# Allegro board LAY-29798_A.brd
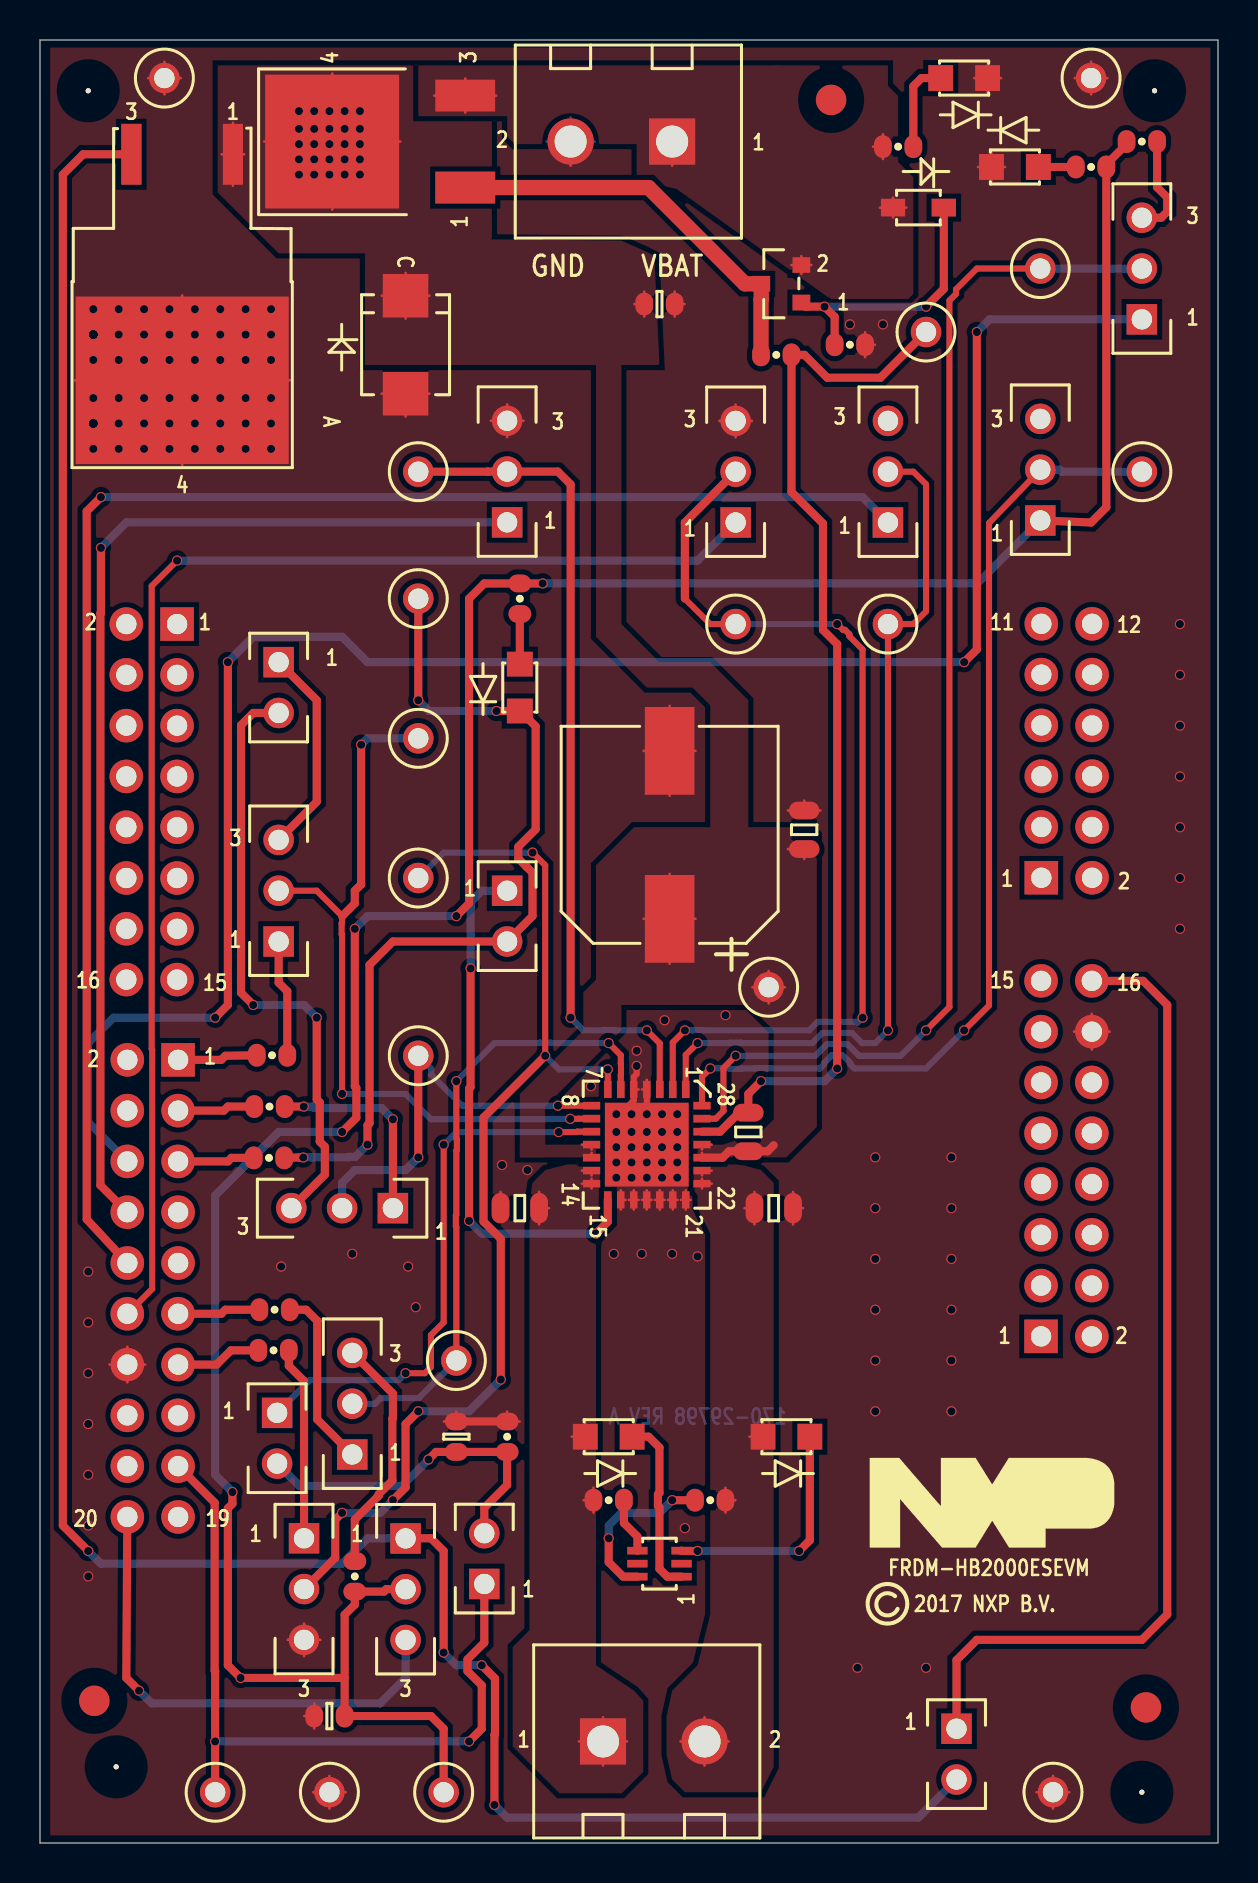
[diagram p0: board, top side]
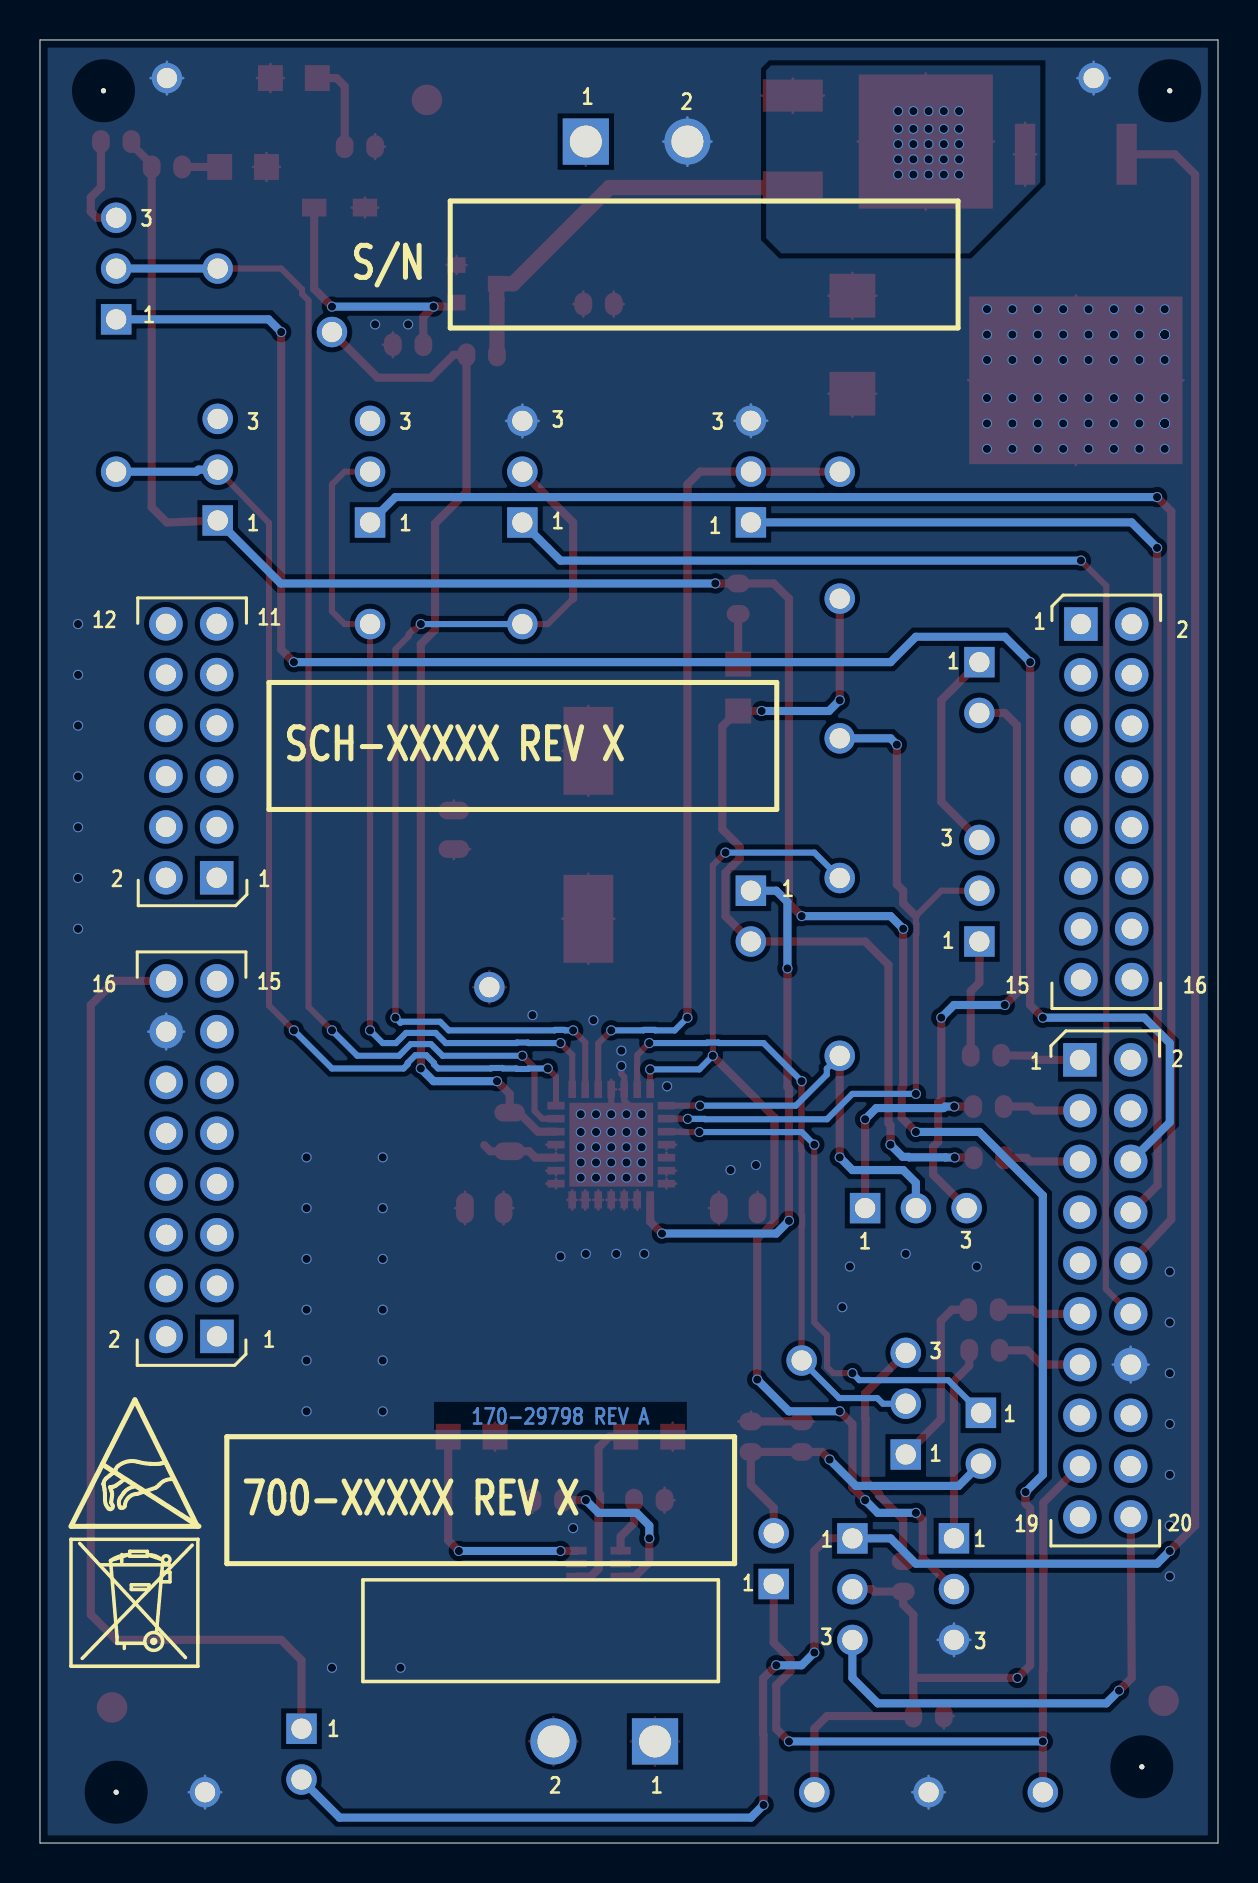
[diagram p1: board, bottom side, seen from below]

Outline 58.93 x 90.17 mm; copper layers: TOP, LAYER2, LAYER3, BOTTOM. Coordinates in mm from the lower left corner of the outline.
Outline path: 0,90.17 0,0 58.93,0 58.93,90.17 0,90.17

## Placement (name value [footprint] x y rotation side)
C1  0.1 UF  [CC0805_OV]  38.23 50.67 90 top
C2  100UF  [CAP_10DIA_10P5]  31.5 50.42 90 top
C3  0.1 UF  [CC0805_OV]  35.43 35.56 90 top
C4  0.033UF  [CC0805_OV]  36.7 31.75 0 top
C5  0.033UF  [CC0805_OV]  24 31.75 180 top
C7  0.33UF  [CC0603_OV]  30.99 76.96 0 top
C8  0.1uF  [CC0603_OV]  14.48 6.35 180 top
C9  0.047UF  [CC0603_OV]  20.83 20.32 90 top
CCP  TEST POINT BLACK  [TEST_LOOP]  44.32 75.56 0 top
CFB  HDR_1X2  [HDR102]  11.86 21.51 0 top
CFB_R  HDR_1X2  [HDR102]  22.22 12.95 180 top
CFB_V  TEST POINT BLACK  [TEST_LOOP]  8.76 2.54 0 top
CS_B  HDR_1X3  [HDR103]  55.12 76.2 180 top
CS_B1  TEST POINT BLACK  [TEST_LOOP]  50.04 78.74 0 top
D57  BAS70TW-7-F  [SC70-6]  30.99 13.97 90 top
D58  1N4148WS  [SOD323]  43.94 81.79 90 top
D59  SMBJ40  [DO-214AA_A]  18.29 74.93 270 top
DIS  HDR_1X3  [HDR103]  13.21 15.24 0 top
DIS1  TEST POINT BLACK  [TEST_LOOP]  18.92 48.26 0 top
ENBL  HDR_1X3  [HDR103]  15.62 19.43 180 top
ENBL1  TEST POINT BLACK  [TEST_LOOP]  20.83 24.13 0 top
EX_IN  HDR_1X2  [HDR102]  11.94 59.05 0 top
FS_B  RED  [LED2_2P34_2P1X1P25]  24 57.79 90 top
FS_B1  TEST POINT BLACK  [TEST_LOOP]  18.92 62.23 0 top
FS_B_  HDR_1X2  [HDR102]  23.37 47.62 0 top
FWD  GREEN  [LED2_2P34_2P1X1P25]  28.45 20.32 180 top
GND  TEST POINT BLACK  [TEST_LOOP]  50.67 2.54 0 top
GND1  TEST POINT BLACK  [TEST_LOOP]  14.48 2.54 0 top
GND2  TEST POINT BLACK  [TEST_LOOP]  6.22 88.27 0 top
GND3  TEST POINT BLACK  [TEST_LOOP]  52.58 88.27 0 top
IN1  HDR_1X3  [HDR103]  11.94 45.09 180 top
IN2  HDR_1X3  [HDR103]  17.65 31.75 270 top
IN_1  TEST POINT BLACK  [TEST_LOOP]  18.92 55.25 0 top
IN_2  TEST POINT BLACK  [TEST_LOOP]  18.92 39.37 0 top
J10  HDR_10X2  [HDR210]  6.91 39.17 180 bottom
J20  CON 1X2 TB TH  [CONN_2_TB_5P08_TH]  31.62 85.09 180 top
J23  HDR_2X6  [HDR206]  50.09 48.27 0 bottom
J24  HDR_2X8  [HDR208]  6.86 60.96 180 bottom
J25  HDR_2X8  [HDR208]  50.08 25.34 0 bottom
MISO  HDR_1X3  [HDR103]  42.42 66.04 180 top
MISO1  TEST POINT BLACK  [TEST_LOOP]  42.42 60.96 0 top
MOSI  HDR_1X3  [HDR103]  23.37 66.05 180 top
MOSI1  TEST POINT BLACK  [TEST_LOOP]  18.92 68.58 0 top
NOREF  -  [unnamed]  55.75 87.63 0 top
NOREF#2  -  [#2]  27.35 37.92 90 top
NOREF#3  -  [#2]  0 0 90 top
NOREF#4  -  [#2]  3.15 2.73 0 top
NOREF#5  -  [unnamed]  55.12 2.54 0 top
NOREF#6  -  [#2]  -232.03 -139.7 0 top
NOREF#7  -  [#2]  38.43 11.38 0 top
NOREF#8  -  [#2]  -345.44 312.17 0 top
NOREF#9  -  [unnamed]  3.81 3.81 0 top
NOREF#10  -  [unnamed]  55.32 6.78 0 top
NOREF#11  -  [unnamed]  2.72 7.11 0 top
NOREF#12  -  [#2]  0 90.17 0 top
NOREF#13  -  [#2]  21.77 38.14 0 top
NOREF#14  -  [#2]  28.4 32.16 0 top
NOREF#15  -  [#2]  28.4 32.16 90 top
NOREF#16  -  [#2]  28.4 32.16 90 top
NOREF#17  -  [#2]  28.4 32.16 0 top
NOREF#18  -  [unnamed]  39.57 87.17 0 top
NOREF#19  -  [#2]  46.15 12.32 0 top
NOREF#20  -  [#2]  41.5 14.77 0 top
NOREF#21  -  [#2]  27.35 37.92 90 top
NOREF#22  -  [#2]  -390.4 -204.85 0 top
NOREF#23  -  [#2]  58.93 0 90 top
NOREF#24  -  [#2]  21.35 43.92 0 top
NOREF#25  -  [#2]  -18.42 -37.46 0 top
NOREF#26  -  [#2]  79.04 90.25 0 top
NOREF#27  -  [#2]  -83.69 -91.31 0 top
NOREF#28  -  [#2]  37.82 8.05 0 top
NOREF#29  -  [#2]  31.5 54.62 270 top
NOREF#30  -  [unnamed]  2.41 87.63 0 top
NOREF#31  -  [#2]  21.35 43.92 0 top
NOREF#32  -  [#2]  0 0 0 top
NOREF#33  -  [#2]  56.77 14.1 180 bottom
NOREF#34  -  [#2]  54.86 4.58 180 bottom
NOREF#35  -  [#2]  42.77 8.08 180 bottom
NOREF#36  -  [#2]  91.19 56.69 180 bottom
NOREF#37  -  [#2]  95.55 47.22 180 bottom
NOREF#38  -  [#2]  92.1 65.66 180 bottom
OUT  CON 1X2 TB TH  [CONN_2_TB_5P08_TH]  28.16 5.08 0 top
Q1  IPD30N06S2-15  [TO252_DPAK_ST]  17.02 85.09 90 top
Q3  SMMBTA06LT1G  [SOT23_A]  37.08 77.98 90 top
R1  1M  [RC0603_OV]  36.83 74.42 0 top
R2  47K  [RC0603_OV]  40.51 74.93 0 top
R10  10K  [RC0603_OV]  42.93 84.84 0 top
R187  0  [RC0603_OV]  11.61 39.4 0 top
R188  0  [RC0603_OV]  11.48 36.83 0 top
R192  0  [RC0603_OV]  11.73 26.67 0 top
R193  0  [RC0603_OV]  11.68 24.64 0 top
R203  1K  [RC0603_OV]  33.53 17.14 0 top
R204  1K  [RC0603_OV]  28.45 17.14 0 top
R206  4.70K  [RC0603_OV]  24 62.23 270 top
R207  4.70K  [RC0603_OV]  52.58 83.82 180 top
R208  4.70K  [RC0603_OV]  55.12 85.09 180 top
R209  4.70K  [RC0603_OV]  15.75 13.34 270 top
R210  0  [RC0603_OV]  11.46 34.26 0 top
R212  200  [RC0603_OV]  23.37 20.32 90 top
REV  RED  [LED2_2P34_2P1X1P25]  37.34 20.32 180 top
SCLK  HDR_1X3  [HDR103]  34.8 66.04 180 top
SCLK1  TEST POINT BLACK  [TEST_LOOP]  34.8 60.96 0 top
U2  MC7805ABD2TG  [D2PAK]  7.11 73.66 180 top
U3  MC33HB2000ES  [QFN28_0P65_6X6_EP4P2]  30.35 34.92 270 top
VBAT  GREEN  [LED2_2P34_2P1X1P25]  46.23 88.27 180 top
VDD  HDR_1X3  [HDR103]  18.29 15.23 0 top
VDD1  TEST POINT BLACK  [TEST_LOOP]  20.19 2.54 0 top
VDD_  GREEN  [LED2_2P34_2P1X1P25]  48.77 83.82 0 top
VDD_REG  HDR_1X2  [HDR102]  45.85 5.71 0 top
VDDQ  HDR_1X3  [HDR103]  50.04 66.14 180 top
VDDQ1  TEST POINT BLACK  [TEST_LOOP]  55.12 68.58 0 top
VPWR  TEST POINT BLACK  [TEST_LOOP]  36.45 42.8 0 top

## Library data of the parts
C1 C3-C5 C7-C9 = CAP_NP
C2 = CAP_POL
CCP CFB_V CS_B1 DIS1 ENBL1 FS_B1 GND GND1-GND3 IN_1 IN_2 MISO1 MOSI1 SCLK1 VDD1 VDDQ1 VPWR = TestLoop
CFB CFB_R EX_IN FS_B_ J20 OUT VDD_REG = CONN_HDR_2X1
CS_B DIS ENBL IN1 IN2 MISO MOSI SCLK VDD VDDQ = Jumper 3Pin
D57 = BAS70TW
D58 = DIODE
D59 = DIODE_TVS
FS_B FWD REV VBAT VDD_ = LED
J10 = CONN_HDR_10X2
J23 = CONN_HDR_6X2
J24 J25 = CONN_HDR_8X2
Q1 = MOSFET_N_D4
Q3 = NPN
R1 R2 R10 R187 R188 R192 R193 R203 R204 R206-R210 R212 = RES
U2 = MC7805
U3 = MC33HB2000EP_QFN_28P

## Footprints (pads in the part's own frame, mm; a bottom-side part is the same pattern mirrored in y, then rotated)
CAP_10DIA_10P5
  rect 4.394x2.489 smd: 1(-4.2,0) 2(4.2,0)
CC0603_OV
  oval 0.889x1.143 smd: 1(-0.762,0) 2(0.762,0)
CC0805_OV
  oval 0.889x1.524 smd: 1(-0.965,0) 2(0.965,0)
CONN_2_TB_5P08_TH
  rect 2.311x2.311 hole 1.6: 1(0,0)
  round 2.311 hole 1.6: 2(5.08,0)
D2PAK
  rect 1.016x3.048 smd: 1(-2.54,-10.795) 3(2.54,-10.795)
  rect 10.668x8.382 smd: 4(0,0.508)
DO-214AA_A
  rect 2.184x2.286 smd: A(2.45,0) C(-2.45,0)
HDR102
  rect 1.524x1.524 hole 1.016: 1(0,0)
  round 1.524 hole 1.016: 2(0,-2.54)
HDR103
  rect 1.524x1.524 hole 1.016: 1(0,0)
  round 1.524 hole 1.016: 2(0,-2.54) 3(0,-5.08)
HDR206
  rect 1.676x1.676 hole 1.016: 1(0,0)
  round 1.676 hole 1.016: 2(2.54,0) 3(0,-2.54) 4(2.54,-2.54) 5(0,-5.08) 6(2.54,-5.08) 7(0,-7.62) 8(2.54,-7.62) 9(0,-10.16) 10(2.54,-10.16) 11(0,-12.7) 12(2.54,-12.7)
HDR208
  rect 1.676x1.676 hole 1.016: 1(0,0)
  round 1.676 hole 1.016: 2(2.54,0) 3(0,-2.54) 4(2.54,-2.54) 5(0,-5.08) 6(2.54,-5.08) 7(0,-7.62) 8(2.54,-7.62) 9(0,-10.16) 10(2.54,-10.16) 11(0,-12.7) 12(2.54,-12.7) 13(0,-15.24) 14(2.54,-15.24) 15(0,-17.78) 16(2.54,-17.78)
HDR210
  rect 1.676x1.676 hole 1.016: 1(0,0)
  round 1.676 hole 1.016: 2(2.54,0) 3(0,-2.54) 4(2.54,-2.54) 5(0,-5.08) 6(2.54,-5.08) 7(0,-7.62) 8(2.54,-7.62) 9(0,-10.16) 10(2.54,-10.16) 11(0,-12.7) 12(2.54,-12.7) 13(0,-15.24) 14(2.54,-15.24) 15(0,-17.78) 16(2.54,-17.78) 17(0,-20.32) 18(2.54,-20.32) 19(0,-22.86) 20(2.54,-22.86)
LED2_2P34_2P1X1P25
  rect 1.245x1.295 smd: A(1.172,0) C(-1.172,0)
QFN28_0P65_6X6_EP4P2
  rect 0.864x0.381 smd: 1(-2.763,1.95) 2(-2.763,1.3) 3(-2.763,0.65) 4(-2.763,0) 5(-2.763,-0.65) 6(-2.763,-1.3) 7(-2.763,-1.95) 15(2.763,-1.95) 16(2.763,-1.3) 17(2.763,-0.65) 18(2.763,0) 19(2.763,0.65) 20(2.763,1.3) 21(2.763,1.95)
  rect 0.381x0.864 smd: 8(-1.95,-2.763) 9(-1.3,-2.763) 10(-0.65,-2.763) 11(0,-2.763) 12(0.65,-2.763) 13(1.3,-2.763) 14(1.95,-2.763) 22(1.95,2.763) 23(1.3,2.763) 24(0.65,2.763) 25(0,2.763) 26(-0.65,2.763) 27(-1.3,2.763) 28(-1.95,2.763)
  rect 4.191x4.191 smd: 29(0,0)
RC0603_OV
  oval 0.889x1.143 smd: 1(-0.762,0) 2(0.762,0)
SC70-6
  rect 0.381x1.016 smd: 1(-0.65,-1.105) 2(0,-1.105) 3(0.65,-1.105) 4(0.65,1.105) 5(0,1.105) 6(-0.65,1.105)
SOD323
  rect 0.889x1.219 smd: A(0,1.27) C(0,-1.27)
SOT23_A
  rect 0.787x0.889 smd: 1(-0.94,-1.003) 2(0.94,-1.003) 3(0,1.003)
TEST_LOOP
  round 1.524 hole 1.016: 1(0,0)
TO252_DPAK_ST
  rect 1.6x2.997 smd: 1(-2.3,-4.253) 3(2.3,-4.253)
  rect 6.706x6.706 smd: 4(0,2.4)
unnamed
  round 0.254 hole 2.388 unplated: (0,0)

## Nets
GND: C1.2 C2.2 C4.2 C5.2 C7.2 C8.2 C9.2 D59.A DIS.3(PIN3) GND.1(PIN1) GND1.1(PIN1) GND2.1(PIN1) GND3.1(PIN1) J10.14 J20.2 J25.14(B7) MOSI.3(PIN3) R2.2 R212.2 SCLK.3(PIN3) U2.4(GND) U3.4(DGND) U3.5(AGND1) U3.16(PGND1) U3.17(PGND2) U3.18(PGND3) U3.19(PGND4) U3.20(PGND5) U3.21(AGND2) U3.29(EP) VBAT.C(CATHODE) VDD_.C(CATHODE)
VBATT: D58.A(ANODE) J20.1 Q1.3(SOURCE) Q3.2(EMITTER) R10.1
VDD: C8.1 R206.1 R207.1 R208.2 R209.2 VDD.2(PIN2) VDD1.1(PIN1) VDDQ.1(PIN1)
VDD_REG: U2.3(OUT) VDD.1(PIN1) VDD_REG.2
VDDQ: U3.28(VDDQ) VDDQ.2(PIN2) VDDQ1.1(PIN1)
CCP: C3.2 CCP.1(PIN1) R1.2 U3.26(CCP)
CFB: CFB.1 U3.10(CFB)
CFB_READ: CFB_R.1 CFB_V.1(PIN1) J10.17
CS_B: CS_B.2(PIN2) CS_B1.1(PIN1) U3.27(C\S\)
CTRL0: ENBL.1(PIN1) R192.2
CTRL1: DIS.1(PIN1) R193.2
DATA0: IN1.1(PIN1) R187.2
DATA1: IN2.1(PIN1) R188.2
DIS: DIS.2(PIN2) DIS1.1(PIN1) U3.7(DIS)
ENBL: ENBL.2(PIN2) ENBL1.1(PIN1) U3.6(ENBL)
EX_IN1: EX_IN.1 IN1.3(PIN3)
EX_IN2: EX_IN.2 IN2.3(PIN3)
FRDM_VDD: J10.20 VDD.3(PIN3)
FS_B: FS_B.C(CATHODE) FS_B1.1(PIN1) FS_B_.2 R210.2
IN1: IN1.2(PIN2) IN_1.1(PIN1) U3.9(IN1)
IN2: IN2.2(PIN2) IN_2.1(PIN1) U3.8(IN2)
MISO: MISO.2(PIN2) MISO1.1(PIN1) U3.1(MISO)
MOSI: MOSI.2(PIN2) MOSI1.1(PIN1) U3.3(MOSI)
OUT1: C5.1 FWD.A(ANODE) OUT.1 R204.1 U3.13(OUT1_1) U3.14(OUT1_2)
OUT2: C4.1 OUT.2 R203.2 REV.A(ANODE) U3.22(OUT2_1) U3.23(OUT2_2)
SCLK: SCLK.2(PIN2) SCLK1.1(PIN1) U3.2(SCLK)
SPI_CS_B: CS_B.1(PIN1) J10.6
SPI_MISO: J10.10 MISO.1(PIN1)
SPI_MOSI: J10.8 MOSI.1(PIN1)
SPI_SCLK: J10.12 SCLK.1(PIN1)
VPWR: C1.1 C2.1 C3.1 C7.1 D59.C Q1.4(DRAIN) U2.1(IN) U3.11(VPWR1) U3.12(VPWR2) U3.24(VPWR3) U3.25(VPWR4) VPWR.1(PIN1)
N15086994: Q1.1(GATE) Q3.3(COLLECTOR) R1.1
N15515059: ENBL.3(PIN3) R209.1
N15516808: CS_B.3(PIN3) R208.1
N15517603: C9.1 CFB.2 CFB_R.2 R212.1
N15519474: D57.1(A1) FWD.C(CATHODE)
N15519750: D57.3(A3) REV.C(CATHODE)
N15519985: D57.6(C1) R203.1
N15520366: D57.4(C3) R204.2
N15536961: D58.C(CATHODE) Q3.1(BASE) R2.1
N15544276: FS_B_.1 U3.15(F\S\)
N15562112: FS_B.A(ANODE) R206.2
N15568529: J25.16(B8) VDD_REG.1
N155139640: J10.1 R187.1
N155139642: J10.3 R188.1
N155139645: J10.5 R210.1
N155348671: R10.2 VBAT.A(ANODE)
N155584890: R207.2 VDD_.A(ANODE)
N1551396410: J10.11 R192.1
N1551396412: J10.13 R193.1

Pads without a net: D57 2 5; J10 2 4 7 9 15 16 18 19; J23 1 2 3 4 5 6 7 8 9 10 11 12; J24 1 2 3 4 5 6 7 8 9 10 11 12 13 14 15 16; J25 1 2 3 4 5 6 7 8 9 10 11 12 13 15; MISO 3; VDDQ 3

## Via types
v1: diameter 0.508, hole 0.406, TOP to BOTTOM, 242 vias

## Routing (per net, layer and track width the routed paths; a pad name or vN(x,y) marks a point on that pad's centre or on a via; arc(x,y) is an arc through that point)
GND: length 248.9
  TOP w0.127: 1.73,73.15 U2.4 ; U2.4 12.5,73.15 ; U2.4 7.11,77.39 ; U2.4 7.11,68.91 ; 34.8,70.31 SCLK.3 ; SCLK.3 33.98,71.12 ; SCLK.3 35.61,71.12 ; SCLK.3 34.8,71.93 ; GND.1 50.67,3.35 ; GND.1 49.86,2.54 ; GND.1 50.67,1.73 ; GND.1 51.49,2.54 ; 13.72,5.73 C8.2 ; C8.2 13.72,6.97 ; C8.2 13.22,6.35 ; 13.21,9.35 DIS.3 ; DIS.3 12.39,10.16 ; DIS.3 13.21,10.97 ; DIS.3 14.02,10.16 ; v1(5.21,72.26) v1(3.94,70.99) v1(2.67,69.72) ; 31.65,31.68 U3.20 ; U3.20 31.41,32.16 ; U3.20 31.89,32.16 ; U3.20 31.65,32.65 ; 22.55,71.13 MOSI.3 ; MOSI.3 23.37,71.94 ; MOSI.3 23.37,70.31 ; MOSI.3 24.18,71.13 ; C7.2 31.75,77.58 ; C7.2 31.75,76.34 ; C7.2 32.25,76.96 ; 41.28,74.31 R2.2 ; R2.2 41.28,75.55 ; R2.2 41.77,74.93 ; 51.76,88.27 GND3.1 ; GND3.1 52.58,89.08 ; GND3.1 52.58,87.45 ; GND3.1 53.39,88.27 ; U3.21 32.54,32.16 ; U3.21 32.3,31.68 ; U3.21 32.3,32.65 ; U3.21 32.06,32.16 ; 30.11,37.69 U3.4 30.35,38.17 ; v1(6.48,75.44) v1(5.21,76.71) ; v1(9.02,72.26) v1(10.29,70.99) v1(11.56,69.72) ; v1(3.94,72.26) v1(2.67,70.99) ; 23.99,21.08 R212.2 23.37,21.58 ; VBAT.C 47.4,88.96 ; VBAT.C 46.73,88.27 ; VBAT.C 48.07,88.27 ; VBAT.C 47.4,87.57 ; C2.2 31.5,56.87 ; C2.2 32.79,54.62 ; C2.2 31.5,52.37 ; C2.2 30.2,54.62 ; U3.16 29.29,32.16 ; U3.16 29.05,31.68 ; U3.16 29.05,32.65 ; 29.46,32.16 U3.17 ; U3.17 29.94,32.16 ; U3.17 29.7,32.65 ; U3.17 29.7,31.68 ; v1(6.48,72.26) v1(5.21,70.99) v1(3.94,69.72) ; v1(11.56,76.71) v1(10.29,75.44) v1(9.02,74.17) ; GND1.1 15.29,2.54 ; GND1.1 14.48,1.73 ; GND1.1 14.48,3.35 ; GND1.1 13.66,2.54 ; 20.21,21.08 C9.2 20.83,21.58 ; 37.41,51.64 C1.2 ; C1.2 38.23,52.13 ; C1.2 39.04,51.64 ; 47.6,83.12 VDD_.C ; VDD_.C 47.6,84.52 ; VDD_.C 46.92,83.82 ; VDD_.C 48.27,83.82 ; v1(30.35,33.27) v1(30.35,34.04) v1(30.35,34.8) U3.29 30.35,35.2 ; U3.19 31.24,32.16 ; U3.19 31,31.68 ; U3.19 30.76,32.16 ; U3.19 31,32.65 ; v1(10.29,72.26) v1(11.56,70.99) ; U3.5 29.94,37.69 ; GND2.1 7.04,88.27 ; GND2.1 5.41,88.27 ; GND2.1 6.22,87.45 ; GND2.1 6.22,89.08 ; 4.37,23.04 J10.14 ; J10.14 4.37,24.82 ; J10.14 3.48,23.93 ; J10.14 5.26,23.93 ; C5.2 23.04,32.56 ; v1(6.48,74.17) v1(5.21,75.44) v1(3.94,76.71) ; 17.09,72.48 D59.A ; D59.A 19.48,72.48 ; D59.A 18.29,71.34 ; v1(6.48,70.99) v1(5.21,69.72) ; v1(5.21,74.17) v1(3.94,75.44) v1(2.67,76.71) ; U3.18 30.59,32.16 ; U3.18 30.11,32.16 ; U3.18 30.35,32.65 ; U3.18 30.35,31.68 ; v1(10.29,76.71) v1(9.02,75.44) v1(7.75,74.17) ; 51.73,40.58 J25.14 ; J25.14 52.62,39.69 ; J25.14 53.51,40.58 ; J25.14 52.62,41.47 ; v1(10.29,69.72) v1(9.02,70.99) v1(7.75,72.26) ; v1(7.75,75.44) v1(9.02,76.71) ; C4.2 37.67,32.56 ; C4.2 38.16,31.75 ; C4.2 37.67,30.94 ; v1(10.29,74.17) v1(11.56,75.44) ; 26.54,83.88 J20.2 ; v1(7.75,70.99) v1(9.02,69.72) ; v1(3.94,74.17) v1(2.67,75.44)
  TOP w0.305: U3.4 v1(30.35,36.45) v1(30.35,35.56) 30.35,35.2 ; 30.35,35.15 30.18,35.15 29.95,35.39 29.95,35.78 29.76,35.97 28.74,35.97 28.42,36.28 28.42,36.62 28.66,36.86 29.42,36.86 29.7,37.14 U3.5 29.7,38.31 29.84,38.46 v1(29.84,38.86)
  TOP w0.406: C9.2 R212.2
  LAYER2 w0.127: J20.2 27.75,85.09 ; J20.2 25.34,85.09 ; J20.2 26.54,86.3 ; J20.2 26.54,83.88 ; 23.37,70.31 MOSI.3 ; MOSI.3 24.18,71.13 ; MOSI.3 22.55,71.13 ; MOSI.3 23.37,71.94 ; 13.21,9.35 DIS.3 ; DIS.3 12.39,10.16 ; DIS.3 14.02,10.16 ; DIS.3 13.21,10.97 ; 49.86,2.54 GND.1 ; GND.1 50.67,1.73 ; GND.1 51.49,2.54 ; GND.1 50.67,3.35 ; 3.48,23.93 J10.14 ; J10.14 5.26,23.93 ; J10.14 4.37,23.04 ; J10.14 4.37,24.82 ; 14.48,1.73 GND1.1 ; GND1.1 13.66,2.54 ; GND1.1 14.48,3.35 ; GND1.1 15.29,2.54 ; SCLK.3 35.61,71.12 ; SCLK.3 33.98,71.12 ; SCLK.3 34.8,71.93 ; SCLK.3 34.8,70.31 ; 51.76,88.27 GND3.1 ; GND3.1 53.39,88.27 ; GND3.1 52.58,87.45 ; GND3.1 52.58,89.08 ; GND2.1 7.04,88.27 ; GND2.1 5.41,88.27 ; GND2.1 6.22,87.45 ; GND2.1 6.22,89.08 ; 51.73,40.58 J25.14 ; J25.14 52.62,41.47 ; J25.14 52.62,39.69 ; J25.14 53.51,40.58
  LAYER3 w0.127: GND2.1 6.22,89.08 ; GND2.1 6.22,87.45 ; GND2.1 5.41,88.27 ; GND2.1 7.04,88.27 ; J20.2 26.54,86.3 ; J20.2 26.54,83.88 ; J20.2 27.75,85.09 ; J20.2 25.34,85.09 ; GND.1 51.49,2.54 ; GND.1 49.86,2.54 ; GND.1 50.67,3.35 ; GND.1 50.67,1.73 ; 52.62,39.69 J25.14 ; J25.14 52.62,41.47 ; J25.14 51.73,40.58 ; J25.14 53.51,40.58 ; GND1.1 15.29,2.54 ; GND1.1 14.48,1.73 ; GND1.1 13.66,2.54 ; GND1.1 14.48,3.35 ; 34.8,70.31 SCLK.3 ; SCLK.3 35.61,71.12 ; SCLK.3 34.8,71.93 ; SCLK.3 33.98,71.12 ; GND3.1 52.58,89.08 ; GND3.1 51.76,88.27 ; GND3.1 53.39,88.27 ; GND3.1 52.58,87.45 ; J10.14 4.37,24.82 ; J10.14 3.48,23.93 ; J10.14 4.37,23.04 ; J10.14 5.26,23.93 ; MOSI.3 24.18,71.13 ; MOSI.3 23.37,70.31 ; MOSI.3 23.37,71.94 ; MOSI.3 22.55,71.13 ; DIS.3 13.21,10.97 ; DIS.3 13.21,9.35 ; DIS.3 12.39,10.16 ; DIS.3 14.02,10.16
  BOTTOM w0.127: 33.98,71.12 SCLK.3 ; SCLK.3 35.61,71.12 ; SCLK.3 34.8,70.31 ; SCLK.3 34.8,71.93 ; 12.39,10.16 DIS.3 ; DIS.3 13.21,10.97 ; DIS.3 14.02,10.16 ; DIS.3 13.21,9.35 ; 5.41,88.27 GND2.1 ; GND2.1 6.22,89.08 ; GND2.1 6.22,87.45 ; GND2.1 7.04,88.27 ; MOSI.3 23.37,71.94 ; MOSI.3 23.37,70.31 ; MOSI.3 24.18,71.13 ; MOSI.3 22.55,71.13 ; J10.14 5.26,23.93 ; J10.14 3.48,23.93 ; J10.14 4.37,23.04 ; J10.14 4.37,24.82 ; 52.58,87.45 GND3.1 ; GND3.1 51.76,88.27 ; GND3.1 52.58,89.08 ; GND3.1 53.39,88.27 ; GND1.1 15.29,2.54 ; GND1.1 14.48,3.35 ; GND1.1 14.48,1.73 ; GND1.1 13.66,2.54 ; GND.1 51.49,2.54 ; GND.1 50.67,1.73 ; GND.1 49.86,2.54 ; GND.1 50.67,3.35 ; J25.14 52.62,41.47 ; J25.14 53.51,40.58 ; J25.14 52.62,39.69 ; J25.14 51.73,40.58 ; J20.2 26.54,86.3 ; J20.2 26.54,83.88 ; J20.2 27.75,85.09 ; J20.2 25.34,85.09
  vias: v1(2.41,28.57) v1(2.41,26.04) v1(2.41,23.49) v1(2.41,20.95) v1(2.41,18.41) v1(2.41,15.88) v1(2.41,13.34) v1(2.67,74.17) v1(2.67,72.26) v1(6.48,76.71) v1(6.48,69.72) v1(7.75,76.71) v1(7.75,69.72) v1(11.56,74.17) v1(11.56,72.26) v1(12.07,28.83) v1(15.62,29.46) v1(18.41,28.83) v1(18.8,26.8) v1(23.11,33.91) v1(24.38,33.66) v1(27.56,37.85) v1(28.7,29.46) v1(28.83,36.45) v1(28.83,35.56) v1(28.83,34.8) v1(28.83,34.04) v1(28.83,33.27) v1(29.59,36.45) v1(29.59,35.56) v1(29.59,34.8) v1(29.59,34.04) v1(29.59,33.27) v1(29.84,39.62) v1(30.1,29.46) v1(31.11,36.45) v1(31.11,35.56) v1(31.11,34.8) v1(31.11,34.04) v1(31.11,33.27) v1(31.24,41.15) v1(31.62,29.46) v1(31.88,36.45) v1(31.88,35.56) v1(31.88,34.8) v1(31.88,34.04) v1(31.88,33.27) v1(32.26,15.75) v1(32.89,29.34) v1(34.29,41.4) v1(40.51,75.95) v1(40.89,8.76) v1(41.78,34.29) v1(41.78,31.75) v1(41.78,29.21) v1(41.78,26.67) v1(41.78,24.13) v1(41.78,21.59) v1(42.16,75.95) v1(44.32,8.76) v1(45.59,34.29) v1(45.59,31.75) v1(45.59,29.21) v1(45.59,26.67) v1(45.59,24.13) v1(45.59,21.59) v1(57.02,60.96) v1(57.02,58.42) v1(57.02,55.88) v1(57.02,53.34) v1(57.02,50.8) v1(57.02,48.26) v1(57.02,45.72)
VBATT: length 11.9
  TOP w0.127: R10.1 42.16,85.46 ; R10.1 41.67,84.84 ; R10.1 42.16,84.21 ; 21.27,86.54 Q1.3 ; Q1.3 21.27,88.24 ; Q1.3 19.72,87.39 ; Q1.3 22.82,87.39 ; 42.67,81.29 D58.A ; D58.A 42.67,82.28 ; D58.A 42.01,81.79 ; D58.A 43.33,81.79 ; Q3.2 38.58,78.92 ; Q3.2 38.09,78.47 ; Q3.2 37.59,78.92 ; Q3.2 38.09,79.36 ; 31.62,83.88 J20.1
VDD: length 139.6
  TOP w0.406: v1(25.15,62.99) R206.1 22.22,62.99 21.46,62.23 21.46,46.99 v1(20.83,46.36) ; v1(15.11,35.56) 15.82,36.27 15.82,37.76 15.75,37.84 v1(15.75,45.72) ; 15.24,8.26 v1(10.03,8.26) 9.4,8.89 9.4,16.74 9.63,16.97 v1(9.63,17.55) ; 15.24,8.26 C8.1 19.56,6.35 20.19,5.71 VDD1.1 ; 15.24,8.26 15.24,11.42 15.75,11.93 R209.2 17.2,12.57 17.32,12.69 VDD.2 ; VDDQ.1 52.58,66.04 53.34,66.8 R207.1 53.34,83.95 54.36,84.96 R208.2
  BOTTOM w0.406: VDDQ.1 46.89,62.99 v1(25.15,62.99) ; v1(20.83,46.36) 16.38,46.36 v1(15.75,45.72) ; v1(9.63,17.55) 8.76,18.41 8.76,32.38 11.94,35.56 v1(15.11,35.56)
VDD_REG: length 130.7
  TOP w0.406: v1(22.1,8.89) 22.76,8.23 22.76,5.44 22.73,5.42 v1(22.73,1.91) ; U2.3 2.16,84.45 1.14,83.44 1.14,15.88 v1(2.41,14.61) ; v1(20.19,9.53) 20.19,14.61 19.56,15.24 18.29,15.24 VDD.1
  BOTTOM w0.406: VDD.1 16.38,15.23 15.11,13.97 3.05,13.97 v1(2.41,14.61) ; v1(22.73,1.91) 23.37,1.27 43.94,1.27 VDD_REG.2 ; v1(20.19,9.53) 20.83,8.89 v1(22.1,8.89)
VDDQ: length 50.9
  TOP w0.305: VDDQ.2 47.47,66.01 47.47,41.88 v1(46.23,40.64) ; U3.28 33.12,38.32 v1(33.53,38.73)
  BOTTOM w0.305: v1(33.53,38.73) 34.5,38.73 34.52,38.71 35.07,38.71 35.1,38.73 35.77,38.73 35.79,38.76 36.34,38.76 36.37,38.73 39.02,38.73 39.22,38.94 39.22,39.01 39.6,39.4 40.15,39.4 40.54,39.01 40.54,38.94 40.74,38.73 44.32,38.73 v1(46.23,40.64)
  BOTTOM w0.406: VDDQ1.1 51.1,68.58 51,68.68 VDDQ.2
CCP: length 53.4
  TOP w0.406: CCP.1 42.04,73.28 39.38,73.28 38.24,74.42 R1.2 37.59,67.56 39.17,65.99 39.17,60.67 39.88,59.95 v1(39.88,38.73) ; v1(36.07,38.1) 35.43,37.47 C3.2 34.97,36.53 34.02,35.57 U3.26
  BOTTOM w0.406: v1(39.88,38.73) 39.24,38.1 v1(36.07,38.1)
CFB: length 27.7
  TOP w0.305: v1(20.19,34.92) 20.19,26.04 19.56,25.4 19.56,23.8 19.25,23.49 v1(18.29,23.49) ; U3.10 26.87,35.57 26.85,35.55 v1(25.94,35.55)
  BOTTOM w0.305: v1(18.29,23.49) 17.94,23.15 13.5,23.15 CFB.1 ; v1(25.94,35.55) 20.82,35.55 v1(20.19,34.92)
CFB_READ: length 38.6
  TOP w0.406: J10.17 8.74,17.02 8.74,8.62 8.76,8.59 v1(8.76,5.08) CFB_V.1 ; v1(21.46,5.08) 22.1,5.71 22.1,7.88 21.39,8.6 21.39,9.18 22.22,10.02 CFB_R.1
  BOTTOM w0.406: v1(21.46,5.08) v1(8.76,5.08)
CS_B: length 62.2
  TOP w0.305: v1(44.32,40.64) 45.49,41.81 45.49,77.14 45.82,77.47 45.82,77.7 46.86,78.74 CS_B1.1 ; U3.27 33.81,36.22 34.19,36.61 34.19,38.76 v1(34.8,39.37)
  BOTTOM w0.305: v1(44.32,40.64) 43.05,39.37 40.97,39.37 40.38,39.95 39.37,39.95 38.79,39.37 v1(34.8,39.37)
  BOTTOM w0.406: CS_B1.1 CS_B.2
CTRL0: length 9
  TOP w0.406: R192.2 13.31,26.67 13.87,26.11 13.87,21.18 ENBL.1
CTRL1: length 9.7
  TOP w0.406: DIS.1 13.21,23.1 12.45,23.86 R193.2
DATA0: length 5.9
  TOP w0.406: R187.2 12.37,42.6 11.94,43.03 IN1.1
DATA1: length 10.1
  TOP w0.406: R188.2 v1(13.2,36.83) ; v1(17.65,36.2) IN2.1
  BOTTOM w0.406: v1(17.65,36.2) 17.09,36.75 13.73,36.75 13.65,36.83 v1(13.2,36.83)
DIS: length 56.1
  TOP w0.305: U3.7 v1(28.4,38.69) ; v1(24.64,49.53) 25.27,48.9 v1(25.27,39.37)
  TOP w0.406: v1(23.05,23.18) 23.05,30.22 22.19,31.08 22.19,36.28 v1(25.27,39.37) ; v1(17.65,17.14) 18.29,17.78 18.29,20.95 v1(18.92,21.59) ; DIS.2 14.77,14.26 14.77,16.17 v1(15.11,16.51)
  BOTTOM w0.305: v1(24.64,49.53) 20.19,49.53 DIS1.1 ; v1(25.27,39.37) 25.95,38.69 v1(28.4,38.69)
  BOTTOM w0.406: v1(15.11,16.51) 17.02,16.51 v1(17.65,17.14) ; v1(23.05,23.18) 21.46,21.59 v1(18.92,21.59)
ENBL: length 31.1
  TOP w0.305: ENBL1.1 20.83,30.82 20.8,30.84 20.8,31.39 20.83,31.41 20.83,34.63 20.85,34.65 20.85,35.2 20.83,35.22 v1(20.83,38.1) ; U3.6 29.05,38.41 29.06,38.42 29.06,38.96 29.05,38.97 29.05,39.4 v1(28.45,40.01)
  BOTTOM w0.305: ENBL.2 16.76,21.97 17.04,22.25 18.95,22.25 ENBL1.1 ; v1(20.83,38.1) 22.73,40.01 24.97,40.01 25,40.03 25.55,40.03 25.57,40.01 v1(28.45,40.01)
EX_IN1: length 10.5
  TOP w0.406: EX_IN.1 13.84,57.15 13.84,52.07 IN1.3
EX_IN2: length 30.2
  TOP w0.406: EX_IN.2 10.67,56.52 10.06,55.91 10.06,42.52 v1(10.67,41.91) ; v1(13.84,41.28) 13.84,37.19 14,37.04 14,35.08 14.25,34.82 14.25,33.43 IN2.3
  BOTTOM w0.406: v1(10.67,41.91) 13.21,41.91 v1(13.84,41.28)
FRDM_VDD: length 25
  TOP w0.406: v1(4.95,7.62) 4.32,8.26 J10.20
  BOTTOM w0.406: VDD.3 18.29,8.26 17.02,6.98 5.59,6.98 v1(4.95,7.62)
FS_B: length 44.3
  TOP w0.406: R210.2 12.95,34.28 v1(13.17,34.28) ; v1(18.92,57.15) FS_B1.1 ; v1(22.83,56.61) FS_B.C 24.03,56.61 24.79,55.85 24.79,50.69 23.93,49.82 23.93,49.24 24.34,48.82 24.64,48.53 24.64,46.36 FS_B_.2 17.65,45.09 16.48,43.92 16.48,36 16.38,35.9 v1(16.38,34.92)
  BOTTOM w0.406: v1(18.92,57.15) 19.46,56.61 v1(22.83,56.61) ; v1(16.38,34.92) 15.77,34.32 15.47,34.32 15.45,34.29 13.63,34.29 13.63,34.28 v1(13.17,34.28)
IN1: length 37.6
  TOP w0.305: IN1.2 13.84,47.62 15.11,46.36 15.11,46.02 15.09,45.99 15.09,45.45 15.11,45.42 v1(15.11,37.47) ; U3.9 26.94,36.22 26.93,36.21 v1(26.52,36.21)
  TOP w0.406: v1(16.07,54.93) 16.07,47.94 15.75,47.62 15.75,46.99 15.11,46.36
  BOTTOM w0.305: v1(15.11,37.47) 18.29,37.47 19.56,36.2 25.65,36.2 25.67,36.21 v1(26.52,36.21)
  BOTTOM w0.406: IN_1.1 16.38,55.25 v1(16.07,54.93)
IN2: length 20.6
  TOP w0.305: U3.8 v1(25.91,36.87)
  TOP w0.406: v1(18.92,34.29) IN_2.1
  BOTTOM w0.305: IN_2.1 19.57,38.72 19.57,38.42 21.12,36.87 v1(25.91,36.87)
  BOTTOM w0.406: v1(18.92,34.29) 18.29,33.66 15.75,33.66 15.11,33.02 IN2.2
MISO: length 43.8
  TOP w0.305: v1(32.89,40.01) 32.3,39.41 U3.1 ; v1(42.42,40.64) MISO1.1 43.69,60.96 44.32,61.59 44.32,67.95 43.69,68.58 MISO.2
  BOTTOM w0.305: v1(42.42,40.64) 41.78,40.01 41.12,40.01 40.62,40.51 39.14,40.51 38.63,40.01 35.1,40.01 35.07,40.03 34.52,40.03 34.5,40.01 v1(32.89,40.01)
MOSI: length 41.9
  TOP w0.305: U3.3 31,39.99 v1(30.35,40.64)
  TOP w0.406: MOSI1.1 22.4,68.58 22.4,68.59 MOSI.2 25.9,68.59 26.54,67.95 v1(26.54,41.28)
  BOTTOM w0.305: v1(26.54,41.28) 27.18,40.64 28.15,40.64 28.17,40.67 28.72,40.67 28.75,40.64 v1(30.35,40.64)
OUT1: length 12.5
  TOP w0.127: U3.14 27.59,33.22 ; U3.14 27.11,32.98 ; U3.14 27.59,32.73 ; R204.1 27.69,17.77 ; R204.1 27.19,17.14 ; R204.1 27.69,16.52 ; 27.59,33.38 U3.13 27.11,33.63 ; C5.1 24.97,32.56 ; C5.1 24.97,30.94 ; C5.1 25.46,31.75 ; 26.6,20.32 FWD.A ; FWD.A 27.28,21.02 ; FWD.A 27.28,19.62 ; 26.96,5.08 OUT.1 ; OUT.1 28.16,3.87 ; OUT.1 29.37,5.08 ; OUT.1 28.16,6.29
OUT2: length 12.5
  TOP w0.127: OUT.2 34.45,5.08 ; OUT.2 33.24,6.29 ; OUT.2 33.24,3.87 ; OUT.2 32.04,5.08 ; 33.12,33.38 U3.23 33.6,33.63 ; R203.2 34.79,17.14 ; R203.2 34.29,17.77 ; R203.2 34.29,16.52 ; C4.1 35.74,32.56 ; C4.1 35.74,30.94 ; C4.1 35.24,31.75 ; 36.17,19.62 REV.A ; REV.A 36.17,21.02 ; REV.A 35.49,20.32 ; 33.12,32.73 U3.22 ; U3.22 33.12,33.22 ; U3.22 33.6,32.98
SCLK: length 48.2
  TOP w0.305: SCLK1.1 33.53,60.96 32.26,62.23 ; U3.2 31.65,40.03 v1(32.26,40.64) ; v1(41.15,41.28) 41.15,59.69 40.49,60.35 40.49,60.45 40.27,60.67 40.17,60.67 v1(39.88,60.96)
  TOP w0.406: SCLK.2 32.26,66.04 32.26,62.23
  BOTTOM w0.305: v1(32.26,40.64) 32.66,40.64 32.69,40.67 33.17,40.67 33.19,40.64 38.48,40.64 38.91,41.07 40.85,41.07 40.9,41.02 v1(41.15,41.28) ; v1(39.88,60.96) SCLK1.1
SPI_CS_B: length 94.8
  TOP w0.406: v1(9.4,59.05) 9.4,41.91 v1(8.76,41.28) ; v1(46.86,75.56) 46.86,59.69 v1(46.23,59.05)
  BOTTOM w0.406: v1(46.86,75.56) 47.5,76.2 CS_B.1 ; v1(46.23,59.05) 16.38,59.05 15.11,60.33 10.67,60.33 v1(9.4,59.05) ; v1(8.76,41.28) 3.68,41.28 2.41,40.01 2.41,36.04 J10.6
SPI_MISO: length 79.3
  TOP w0.406: v1(3.05,67.31) 2.34,66.6 2.34,31.19 J10.10
  BOTTOM w0.406: MISO.1 41.15,67.31 v1(3.05,67.31)
SPI_MOSI: length 54.6
  TOP w0.406: v1(3.05,64.77) 3.05,61.52 3.02,61.5 3.02,32.89 J10.8
  BOTTOM w0.406: MOSI.1 4.32,66.05 v1(3.05,64.77)
SPI_SCLK: length 67.4
  TOP w0.305: J10.12 5.61,27.71 5.61,39.68 5.59,39.71 5.59,62.87 v1(6.86,64.14)
  BOTTOM w0.406: v1(6.86,64.14) 32.89,64.14 SCLK.1
VPWR: length 41.7
  TOP w0.127: 33.12,34.68 U3.25 33.6,34.92 ; Q1.4 18.02,85.09 ; Q1.4 14.62,81.69 ; Q1.4 11.21,85.09 ; Q1.4 14.62,88.49 ; 18.29,76.24 D59.C ; D59.C 19.48,77.38 ; D59.C 17.09,77.38 ; D59.C 18.29,78.52 ; C7.1 30.23,77.58 ; C7.1 30.23,76.34 ; C7.1 29.73,76.96 ; C2.1 31.5,48.47 ; C2.1 30.2,46.22 ; C2.1 32.79,46.22 ; C2.1 31.5,43.97 ; VPWR.1 36.45,43.61 ; VPWR.1 35.64,42.8 ; VPWR.1 37.26,42.8 ; VPWR.1 36.45,41.99 ; 9.09,84.45 U2.1 ; U2.1 9.65,82.88 ; U2.1 10.21,84.45 ; U2.1 9.65,86.03 ; 37.41,49.71 C1.1 38.23,49.21 ; 27.59,34.68 U3.11 27.11,34.92 ; U3.12 27.59,34.52 ; U3.24 33.12,34.52
  TOP w0.406: U3.24 34.15,34.28 34.47,34.59 C3.1 36.4,34.59 36.7,34.9
  vias: v1(12.95,86.61) v1(12.95,85.73) v1(12.95,84.96) v1(12.95,84.2) v1(12.95,83.44) v1(13.72,86.61) v1(13.72,85.73) v1(13.72,84.96) v1(13.72,84.2) v1(13.72,83.44) v1(14.48,86.61) v1(14.48,85.73) v1(14.48,84.96) v1(14.48,84.2) v1(14.48,83.44) v1(15.24,86.61) v1(15.24,85.73) v1(15.24,84.96) v1(15.24,84.2) v1(15.24,83.44) v1(16,86.61) v1(16,85.73) v1(16,84.96) v1(16,84.2) v1(16,83.44)
N15086994: length 20.4
  TOP w0.762: Q1.1 30.44,82.79 35.26,77.98 Q3.3 36.08,77.2 36.07,77.19 R1.1
N15515059: length 12
  TOP w0.406: ENBL.3 17.65,22.48 17.65,21.25 17.63,21.23 17.63,18.13 16.94,17.44 16.94,17.37 15.75,16.17 R209.1
N15516808: length 5.1
  TOP w0.406: R208.1 55.88,82.8 56.39,82.3 56.39,81.58 56.08,81.28 CS_B.3
N15517603: length 17.2
  TOP w0.406: v1(19.43,19.18) 19.81,19.56 C9.1 R212.1 23.37,17.91 22.22,16.76 CFB_R.2
  BOTTOM w0.406: v1(19.43,19.18) 18.11,17.86 12.98,17.86 CFB.2
N15519474: length 9
  TOP w0.406: D57.1 31.38,13.32 30.99,13.71 30.99,16.77 30.91,16.85 30.91,17.44 30.99,17.52 30.99,19.78 30.45,20.32 FWD.C
N15519750: length 11.8
  TOP w0.406: D57.3 32.11,14.61 v1(32.89,14.61) ; v1(37.97,14.61) 38.51,15.14 REV.C
  BOTTOM w0.406: v1(37.97,14.61) v1(32.89,14.61)
N15519985: length 8.4
  TOP w0.406: D57.6 29.17,13.32 28.45,14.04 v1(28.45,15.24) ; v1(31.62,17.14) R203.1
  BOTTOM w0.406: v1(28.45,15.24) 28.45,15.88 29.08,16.51 30.99,16.51 v1(31.62,17.14)
N15520366: length 2.8
  TOP w0.406: R204.2 29.21,16 29.88,15.33 D57.4
N15536961: length 13.8
  TOP w0.406: R2.1 39.75,76.33 v1(39.24,76.84) 38.29,76.84 Q3.1 ; v1(44.32,76.84) 45.21,77.72 D58.C
  BOTTOM w0.406: v1(44.32,76.84) v1(39.24,76.84)
N15544276: length 26.6
  TOP w0.406: U3.15 28.4,31.07 v1(27.81,30.48) ; v1(21.54,43.74) 21.54,37.81 21.46,37.73 v1(21.46,31.11)
  BOTTOM w0.406: v1(21.54,43.74) 21.54,47.07 22.1,47.62 FS_B_.1 ; v1(21.46,31.11) 22.1,30.48 v1(27.81,30.48)
N15562112: length 2.5
  TOP w0.406: FS_B.A R206.2
N15568529: length 49.7
  TOP w0.406: VDD_REG.1 45.85,9.14 46.86,10.16 55.12,10.16 56.39,11.43 56.39,41.91 55.18,43.12 J25.16
N155139640: length 4
  TOP w0.406: R187.1 9.27,39.37 9.07,39.17 J10.1
N155139642: length 3.9
  TOP w0.406: J10.3 9.19,36.63 9.4,36.83 R188.1
N155139645: length 3.9
  TOP w0.406: R210.1 9.58,34.26 9.4,34.09 J10.5
N155348671: length 4.6
  TOP w0.406: VBAT.A 44.09,88.27 43.69,87.86 R10.2
N155584890: length 1.9
  TOP w0.406: VDD_.A R207.2
N1551396410: length 4.1
  TOP w0.406: J10.11 9.07,26.47 9.27,26.67 R192.1
N1551396412: length 4.3
  TOP w0.406: R193.1 9.55,24.64 8.84,23.93 J10.13

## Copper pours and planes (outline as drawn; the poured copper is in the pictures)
GND on TOP: 0.51,89.79 0.51,0.38 58.55,0.38 58.55,89.79 ; 13 cut-outs
GND on BOTTOM, LAYER2, LAYER3: 0.51,89.79 0.51,0.38 58.55,0.38 58.55,89.79
VBATT on TOP: 18.92,88.9 18.92,86.36 23.37,86.36 23.37,85.34 23.75,84.96 33.29,84.96 34.29,86.36 36.83,86.36 37.34,86.87 37.34,88.65 37.08,88.9
VBATT on TOP: 35.56,87.63 29.84,87.63 29.84,83.19 31.84,82.73 39.55,77.22 43.43,77.22 43.69,77.47 43.69,83.31 42.93,84.07 42.93,87.38 42.42,87.88 42.42,88.9 36.7,88.9 35.81,87.88
OUT1 on TOP: 27.99,33.93 26.37,33.93 25.27,33.66 24.64,33.02 24.49,32.05 24.49,10.64 23.65,9.8 23.65,4.83 25.98,2.49 29.11,2.49 30.18,3.56 30.18,7.11 29.72,7.62 27.81,8.89 27.81,29.84 28.04,31.22 28.04,33.88
OUT2 on TOP: 32.66,33.83 32.66,32.69 32.89,32.38 32.89,31.75 33.53,30.48 33.53,11.43 32.89,8.89 31.62,7.62 31.34,6.35 31.34,4.39 31.62,3.17 32.26,2.54 36.07,2.54 36.7,3.81 36.7,33.02 36.07,33.66 35.03,33.93 32.77,33.93
VPWR on TOP: 32.89,34.29 37.34,34.29 38.86,35.81 38.86,50.42 38.48,50.8 29.72,50.8 27.81,48.9 27.81,43.18 29.08,41.91 35.43,41.91 36.7,40.64 36.7,36.2 36.07,35.56 34.16,34.92 32.89,34.92
VPWR on TOP: 8.89,88.9 8.89,82.55 11.94,79.5 21.84,79.5 22.61,80.26 22.61,88.65 22.35,88.9
VPWR on TOP: 27.81,34.92 27.81,34.29 24,34.29 24,34.92
VPWR on TOP: 16.26,80.26 16.26,73.91 30.99,73.91 30.73,79.38 30.23,79.63 29.08,80.14
VPWR on TOP: 24,37.47 24,34.29 25.27,34.29 25.27,36.83 29.08,40.64 29.08,43.18 27.81,43.18 27.18,42.55 27.18,40.64
VPWR on TOP: 27.81,74.93 27.81,60.33 30.35,57.79 32.64,57.79 33.53,56.9 33.53,49.53 34.8,49.53 35.43,50.16 35.43,57.15 33.53,59.05 30.99,59.05 29.08,60.96 29.08,74.93
VPWR on BOTTOM, LAYER2, LAYER3: 8.89,88.9 8.89,83.06 12.45,79.5 21.84,79.5 22.61,80.26 22.61,88.65 22.35,88.9

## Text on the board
BOTTOM: 170-29798 REV A | 1 OF 10 | BOTTOM LAYER
Package Geometry/Pastemask Bottom: 2 OF 10 | PASTEMASK BOTTOM
Ref Des/Silkscreen Bottom: 3 OF 10 | SILKSCREEN BOTTOM
User.Comments: 4 OF 10 | 9 OF 10 | SOLDERMASK BOTTOM | TOP SOLDERMASK
TOP: 7 OF 10 | L1_TOP
Package Geometry/Pastemask Top: 10 OF 10 | TOP PASTEMASK | 16.
Ref Des/Silkscreen Top: 1 | 3 | FRDM-HB2000ESEVM | 11 | 15 | 2 | 12 | 16 | GND | VBAT | 8 OF 10 | TOP SILKSCREEN
LAYER2: 5 OF 10 | LAYER 2
LAYER3: 6 OF 10 | LAYER 3
DIMENSION: GRID ORIGIN | PRIMARY DATUM | 16. | 0 | VIEW FROM PRIMARY SIDE | 17. | 8. | +/- 10%
User.5: 16. BASIC GRID INCREMENT AT 1:1 IS 0.0001.
User.25: FIGURE | SIZE | 16.0 | 40.0 | 63.0 | 94.0 | DRILL CHART: TOP to BOTTOM | ALL UNITS ARE IN MILS | TOLERANCE | +0.0/-0.02 | +3.0/-3.0 | +2.0/-2.0 | PLATED | NON-PLATED | QTY | 242 | 122 | 4
User.27: KKKKK | KIT HB2001EKEVB | GGG
